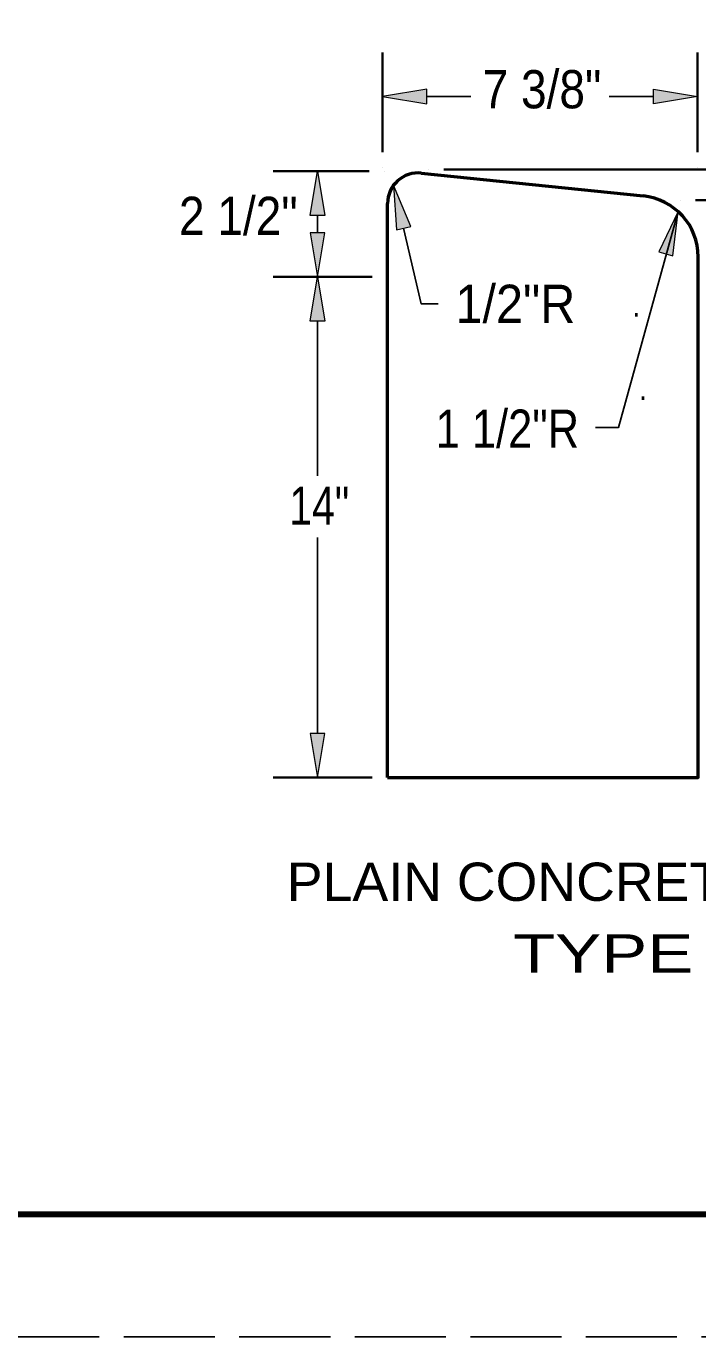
# Model space of a CAD drawing. Extents: x 36.6 to 71.9, y 0.8 to 22.8.
# Drawn here: x 54.49 to 57.24, y 0.78 to 6.13 of the extents above; entities that cross this region are included whole.
import ezdxf

# ---------------------------------------------------------------- set-up
doc = ezdxf.new("R2010")
doc.units = 0
doc.header["$LTSCALE"] = 0.062
doc.linetypes.add('LONG_DASHED', pattern=[7.5, 6, -1.5])
for name, color, linetype, lineweight in [('1', 7, 'Continuous', 13), ('3', 7, 'Continuous', 25), ('8', 7, 'Continuous', 13)]:
    doc.layers.add(name, color=color, linetype=linetype, lineweight=lineweight)

msp = doc.modelspace()

# ---------------------------------------------------------------- hatches: boundary and pattern name
at = {"layer": '1'}
for points in [[(56.13117, 5.81433), (56.13117, 5.87433), (55.95117, 5.84433), (55.95117, 5.84433)], [(57.05733, 5.81433), (57.05733, 5.87433), (57.23733, 5.84433), (57.23733, 5.84433)], [(55.71458, 5.35842), (55.65458, 5.35842), (55.68458, 5.5385), (55.68458, 5.5385)], [(55.71458, 5.28717), (55.65458, 5.28717), (55.68458, 5.10717), (55.68458, 5.10717)], [(55.71458, 4.92717), (55.65458, 4.92717), (55.68458, 5.10717), (55.68458, 5.10717)], [(55.71458, 3.24233), (55.65458, 3.24233), (55.68458, 3.06233), (55.68458, 3.06233)]]:
    msp.add_hatch(color=256, dxfattribs=at).paths.add_polyline_path(points)
at = {"layer": '3'}
for points in [[(56.00725, 5.29942), (56.06575, 5.31292), (55.99592, 5.4815), (55.99592, 5.4815)], [(57.07908, 5.20975), (57.13667, 5.19275), (57.15892, 5.37383), (57.15892, 5.37383)]]:
    msp.add_hatch(color=256, dxfattribs=at).paths.add_polyline_path(points)

# ---------------------------------------------------------------- linework, layer by layer
at = {"layer": '1', "lineweight": 35}
for p, q in [((55.95117, 5.61667), (55.95117, 6.02433)), ((57.23733, 5.61667), (57.23733, 6.02433)), ((55.8965, 5.5385), (55.50458, 5.5385)), ((56.20192, 5.54633), (57.65267, 5.54633)), ((57.22925, 5.42092), (57.65267, 5.42092)), ((55.90867, 5.10717), (55.50458, 5.10717)), ((55.90867, 3.06233), (55.50458, 3.06233))]:
    msp.add_line(p, q, dxfattribs=at)
at = {"layer": '1', "lineweight": 25}
for p, q in [((56.13117, 5.84433), (56.31117, 5.84433)), ((57.05733, 5.84433), (56.87733, 5.84433)), ((55.68458, 5.28717), (55.68458, 5.3585)), ((55.68458, 4.29442), (55.68458, 4.92717)), ((55.68458, 3.24233), (55.68458, 4.04358))]:
    msp.add_line(p, q, dxfattribs=at)
at = {"layer": '1', "lineweight": 53}
for p, q in [((56.10892, 5.53125), (57.01592, 5.43792)), ((55.97117, 3.06233), (55.97117, 5.40692))]:
    msp.add_line(p, q, dxfattribs=at)
at = {"layer": '1'}
msp.add_line((55.74708, 5.10717), (55.86458, 5.10717), dxfattribs=at)
at = {"layer": '1', "linetype": 'LONG_DASHED', "lineweight": 25}
msp.add_line((71.78558, 0.77842), (36.58558, 0.77842), dxfattribs=at)
at = {"layer": '1', "lineweight": 158}
msp.add_lwpolyline([(71.70225, 22.27842), (71.70225, 1.27842), (39.20225, 1.27842)], dxfattribs=at)
at = {"layer": '1'}
for points in [[(56.13117, 5.81433), (56.13117, 5.87433), (55.95117, 5.84433), (55.95117, 5.84433)], [(57.05733, 5.81433), (57.05733, 5.87433), (57.23733, 5.84433), (57.23733, 5.84433)], [(55.71458, 5.35842), (55.65458, 5.35842), (55.68458, 5.5385), (55.68458, 5.5385)], [(55.71458, 5.28717), (55.65458, 5.28717), (55.68458, 5.10717), (55.68458, 5.10717)], [(55.71458, 4.92717), (55.65458, 4.92717), (55.68458, 5.10717), (55.68458, 5.10717)], [(55.71458, 3.24233), (55.65458, 3.24233), (55.68458, 3.06233), (55.68458, 3.06233)]]:
    msp.add_lwpolyline(points, close=True, dxfattribs=at)
at = {"layer": '1', "lineweight": 53}
msp.add_lwpolyline([(55.97117, 3.06233), (57.24033, 3.06233), (57.24033, 5.18917)], dxfattribs=at)
for centre, radius, start, end in [((56.09617, 5.40692), 0.125, 84.12387, 180), ((56.99033, 5.18917), 0.25, 0, 84.12387)]:
    msp.add_arc(centre, radius, start, end, dxfattribs=at)
at = {"layer": '3', "lineweight": 13}
for points in [[(56.00725, 5.29942), (56.06575, 5.31292), (55.99592, 5.4815), (55.99592, 5.4815)], [(57.07908, 5.20975), (57.13667, 5.19275), (57.15892, 5.37383), (57.15892, 5.37383)]]:
    msp.add_lwpolyline(points, close=True, dxfattribs=at)
at = {"layer": '3'}
for points in [[(57.15892, 5.37383), (56.91525, 4.49275), (56.82108, 4.49275)], [(56.0365, 5.30617), (56.108, 4.99742), (56.17858, 4.99742)]]:
    msp.add_lwpolyline(points, dxfattribs=at)
at = {"layer": '8'}
for p, q in [((57.23733, 5.84433), (57.23742, 5.84433)), ((55.68458, 5.5385), (55.68467, 5.5385)), ((55.95117, 5.55417), (55.95125, 5.55417)), ((55.959, 5.5385), (55.95908, 5.5385)), ((56.13942, 5.54633), (56.1395, 5.54633)), ((57.23733, 5.55417), (57.23742, 5.55417)), ((57.16675, 5.42092), (57.16683, 5.42092)), ((55.68458, 5.10717), (55.68467, 5.10717)), ((55.68458, 5.10717), (55.68467, 5.10717)), ((55.97117, 5.10717), (55.97125, 5.10717)), ((55.97117, 3.06233), (55.97125, 3.06233))]:
    msp.add_line(p, q, dxfattribs=at)

# ---------------------------------------------------------------- texts
at = {"layer": '1'}
for s, width, p in [('7 3/8"', 0.9, (56.35983, 5.79575)), ('2 1/2"', 0.9, (55.11917, 5.2785)), ('14"', 0.8, (55.56967, 4.09467))]:
    msp.add_text(s, height=0.1562, dxfattribs=dict(at, width=width)).set_placement(p)
at = {"layer": '3'}
for s, height, width, p in [('1/2"R', 0.1562, 0.95, (56.24883, 4.91925)), ('.', 0.09375, 0.9, (56.97225, 4.94467)), ('.', 0.09375, 0.9, (56.99983, 4.60467)), ('1 1/2"R', 0.1562, 0.85, (56.16775, 4.40925)), ('PLAIN CONCRETE CURBING', 0.1562, 1.05, (55.5595, 2.55883)), ('TYPE IV ', 0.1562, 1.35, (56.48383, 2.26592))]:
    msp.add_text(s, height=height, dxfattribs=dict(at, width=width)).set_placement(p)

doc.saveas('drawing.dxf')
